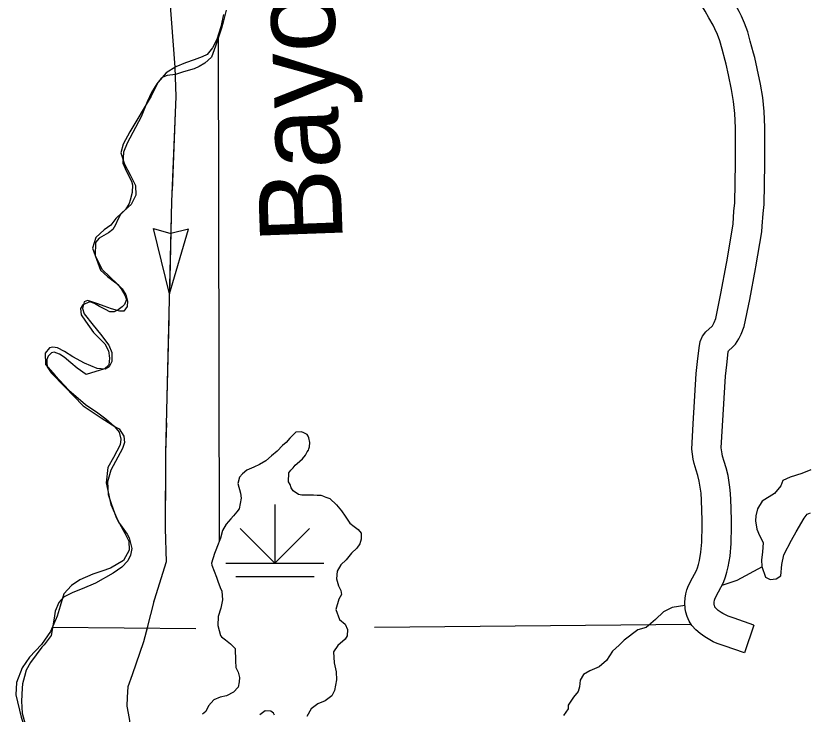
# Model space of a CAD drawing. Extents: x 1373094 to 1376427, y 1168361 to 1170494.
# Drawn here: x 1373397.7 to 1373465.3, y 1169725.9 to 1169785.3 of the extents above; entities that cross this region are included whole.
import ezdxf

# ---------------------------------------------------------------- set-up
doc = ezdxf.new("R2010")
doc.units = 0
doc.layers.add('R_Axis', color=7, linetype='Continuous')

msp = doc.modelspace()

# ---------------------------------------------------------------- linework, layer by layer
at = {"layer": 'R_Axis'}
for p, q in [((1373410.773, 1169761.682), (1373409.424, 1169767.241)), ((1373409.424, 1169767.241), (1373410.885, 1169766.812)), ((1373410.773, 1169761.682), (1373412.384, 1169767.171)), ((1373412.384, 1169767.171), (1373410.905, 1169766.812)), ((1373419.753, 1169743.734), (1373419.753, 1169738.734)), ((1373419.753, 1169738.734), (1373416.806, 1169741.681)), ((1373419.753, 1169738.734), (1373422.699, 1169741.681)), ((1373415.586, 1169738.734), (1373423.919, 1169738.734)), ((1373416.419, 1169737.598), (1373423.086, 1169737.598)), ((1373460.553, 1169733.472), (1373459.741, 1169731.108))]:
    msp.add_line(p, q, dxfattribs=at)
for points in [[(1373412.64, 1169808.408), (1373409.961, 1169801.023), (1373409.712, 1169800.051), (1373409.902, 1169798.585), (1373411.232, 1169780.964)], [(1373458.185, 1169781.213), (1373458.109, 1169781.541), (1373457.84, 1169782.502), (1373457.645, 1169783.212), (1373457.441, 1169783.758), (1373457.227, 1169784.225), (1373457.072, 1169784.541), (1373456.727, 1169785.154), (1373456.391, 1169785.721), (1373456.161, 1169786.091), (1373455.877, 1169786.525), (1373455.671, 1169786.772), (1373455.26, 1169787.252), (1373454.937, 1169787.584), (1373454.807, 1169787.707), (1373454.567, 1169787.915), (1373454.416, 1169788.03)], [(1373460.62, 1169781.779), (1373460.531, 1169782.162), (1373460.249, 1169783.17), (1373460.026, 1169783.981), (1373459.752, 1169784.718), (1373459.485, 1169785.297), (1373459.286, 1169785.704), (1373458.892, 1169786.405), (1373458.537, 1169787.003)], [(1373415.382, 1169785.458), (1373415.152, 1169784.403), (1373414.807, 1169783.312), (1373414.454, 1169782.621), (1373413.983, 1169782.045), (1373413.571, 1169781.854), (1373412.877, 1169781.591), (1373412.151, 1169781.327), (1373411.309, 1169780.994), (1373410.488, 1169780.478), (1373409.821, 1169779.682), (1373409.211, 1169778.502), (1373408.631, 1169777.507), (1373408.003, 1169776.461), (1373407.407, 1169775.449), (1373406.844, 1169774.404), (1373406.625, 1169773.665), (1373406.942, 1169772.704), (1373407.441, 1169771.812), (1373407.89, 1169770.903), (1373407.906, 1169770.069), (1373407.522, 1169769.277), (1373406.737, 1169768.579), (1373406.197, 1169768.085), (1373405.793, 1169767.51), (1373405.218, 1169767.115), (1373404.516, 1169766.451), (1373404.217, 1169765.562), (1373404.9, 1169763.689), (1373405.508, 1169763.15), (1373406.217, 1169762.595), (1373406.741, 1169762.105), (1373407.05, 1169761.593), (1373407.21, 1169761.046), (1373407.185, 1169760.578), (1373406.877, 1169760.188), (1373406.561, 1169760.182), (1373405.826, 1169760.386), (1373405.223, 1169760.608), (1373404.671, 1169760.831), (1373404.069, 1169761.02), (1373403.785, 1169761.099), (1373403.504, 1169760.993), (1373403.365, 1169760.423), (1373403.506, 1169759.975), (1373404.289, 1169759.006), (1373404.902, 1169758.233), (1373405.601, 1169757.311), (1373405.879, 1169756.666), (1373405.859, 1169755.915), (1373405.635, 1169755.46), (1373405.29, 1169755.253), (1373404.607, 1169755.324), (1373403.535, 1169755.771), (1373402.544, 1169756.32), (1373401.838, 1169756.757), (1373401.233, 1169757.063), (1373400.85, 1169757.139), (1373400.568, 1169757.067), (1373400.195, 1169756.61), (1373400.229, 1169755.643), (1373401.028, 1169754.723), (1373402.198, 1169753.46), (1373403.634, 1169752.236), (1373404.661, 1169751.537), (1373405.369, 1169751.017), (1373406.079, 1169750.396), (1373406.504, 1169749.887), (1373406.631, 1169749.288), (1373406.59, 1169748.82), (1373406.012, 1169747.725), (1373405.529, 1169746.882), (1373405.387, 1169745.578), (1373405.77, 1169743.749), (1373406.378, 1169742.376), (1373406.963, 1169741.285), (1373407.308, 1169740.608), (1373407.339, 1169739.857), (1373406.874, 1169738.964), (1373405.756, 1169738.31), (1373405.012, 1169738.062), (1373404.252, 1169737.798)], [(1373415.608, 1169785.815), (1373415.38, 1169784.912), (1373415.216, 1169784.277), (1373414.855, 1169783.274), (1373414.692, 1169782.739), (1373414.364, 1169781.802), (1373413.801, 1169781.299), (1373413.303, 1169781.029), (1373412.872, 1169780.826), (1373411.976, 1169780.555), (1373411.279, 1169780.351), (1373410.581, 1169780.247), (1373410.216, 1169780.111), (1373410.05, 1169779.977), (1373409.687, 1169779.541), (1373409.258, 1169778.804), (1373408.863, 1169778.001), (1373408.37, 1169776.73), (1373407.184, 1169774.487), (1373406.855, 1169773.718), (1373406.793, 1169772.783), (1373407.128, 1169772.084), (1373407.531, 1169771.251), (1373407.632, 1169770.951), (1373407.602, 1169770.283), (1373407.439, 1169769.648), (1373407.34, 1169769.347), (1373407.044, 1169768.845), (1373406.613, 1169768.409), (1373406.383, 1169768.007), (1373406.185, 1169767.539), (1373405.954, 1169767.137), (1373405.59, 1169766.868), (1373405.192, 1169766.632), (1373404.794, 1169766.396), (1373404.464, 1169766.027), (1373404.436, 1169764.892), (1373405.039, 1169763.727), (1373406.375, 1169762.466), (1373406.676, 1169762.1), (1373406.978, 1169761.567), (1373407.112, 1169761.201), (1373406.948, 1169760.766), (1373406.75, 1169760.565), (1373406.418, 1169760.296), (1373406.053, 1169760.127), (1373405.688, 1169760.125), (1373405.321, 1169760.324), (1373404.821, 1169760.588), (1373404.388, 1169760.853), (1373403.988, 1169760.984), (1373403.391, 1169760.747), (1373403.193, 1169760.413), (1373403.262, 1169759.879), (1373403.63, 1169759.347), (1373404.3, 1169758.382), (1373405.268, 1169757.419), (1373405.57, 1169756.82), (1373405.673, 1169756.186), (1373405.609, 1169755.618), (1373405.245, 1169755.283), (1373403.685, 1169754.807), (1373402.918, 1169755.337), (1373402.383, 1169755.802), (1373401.816, 1169756.266), (1373401.416, 1169756.531), (1373400.95, 1169756.695), (1373400.717, 1169756.661), (1373400.453, 1169756.359), (1373400.321, 1169756.091), (1373400.322, 1169755.858), (1373400.357, 1169755.457), (1373400.692, 1169754.958), (1373401.861, 1169753.763), (1373403.431, 1169752.135), (1373404.965, 1169751.108), (1373406.199, 1169750.314), (1373406.499, 1169750.182), (1373406.9, 1169749.55), (1373406.936, 1169749.016), (1373406.772, 1169748.514), (1373406.377, 1169747.778), (1373405.784, 1169746.673), (1373405.489, 1169745.67), (1373405.56, 1169744.602), (1373405.83, 1169743.736), (1373406.201, 1169742.703), (1373406.436, 1169742.236), (1373406.737, 1169741.804), (1373407.172, 1169741.206)], [(1373414.915, 1169783.653), (1373415.01, 1169740.556)], [(1373461.474, 1169772.749), (1373461.495, 1169773.968), (1373461.487, 1169775.288), (1373461.487, 1169775.861), (1373461.433, 1169777.2), (1373461.305, 1169778.381), (1373461.116, 1169779.516), (1373460.839, 1169780.838), (1373460.62, 1169781.779)], [(1373411.232, 1169780.964), (1373411.305, 1169778.46), (1373410.959, 1169769.5), (1373410.452, 1169748.131), (1373410.412, 1169741.702), (1373410.497, 1169738.866), (1373409.464, 1169735.596), (1373408.573, 1169732.046), (1373407.592, 1169729.245), (1373407.24, 1169728.216), (1373407.183, 1169727.346), (1373407.156, 1169726.577), (1373407.338, 1169725.514), (1373407.918, 1169721.692), (1373408.564, 1169716.819), (1373408.889, 1169713.173)], [(1373411.232, 1169780.964), (1373411.282, 1169779.273)], [(1373458.975, 1169772.792), (1373458.995, 1169773.982), (1373458.987, 1169775.281), (1373458.987, 1169775.81), (1373458.938, 1169777.015), (1373458.827, 1169778.041), (1373458.658, 1169779.055), (1373458.398, 1169780.299), (1373458.185, 1169781.212)], [(1373411.252, 1169777.074), (1373410.996, 1169770.479)], [(1373458.232, 1169764.255), (1373458.259, 1169764.396), (1373458.743, 1169767.253), (1373458.774, 1169767.627), (1373458.85, 1169768.706), (1373458.917, 1169769.424), (1373458.975, 1169772.792)], [(1373460.689, 1169763.791), (1373460.72, 1169763.956), (1373461.225, 1169766.939), (1373461.267, 1169767.435), (1373461.342, 1169768.503), (1373461.415, 1169769.287), (1373461.474, 1169772.749)], [(1373410.93, 1169768.28), (1373410.773, 1169761.682)], [(1373455.761, 1169755.91), (1373455.891, 1169757.081), (1373455.979, 1169757.609), (1373456.186, 1169758.07), (1373456.462, 1169758.448), (1373456.99, 1169758.914), (1373457.016, 1169758.942), (1373457.091, 1169759.06), (1373457.17, 1169759.221), (1373457.302, 1169759.583), (1373457.747, 1169761.684), (1373458.232, 1169764.255)], [(1373458.246, 1169755.634), (1373458.368, 1169756.736), (1373458.38, 1169756.806), (1373458.733, 1169757.118), (1373458.996, 1169757.399), (1373459.274, 1169757.832), (1373459.474, 1169758.242), (1373459.711, 1169758.892), (1373460.198, 1169761.193), (1373460.689, 1169763.791)], [(1373410.721, 1169759.483), (1373410.643, 1169756.184)], [(1373410.643, 1169756.184), (1373410.565, 1169752.885)], [(1373455.645, 1169746.657), (1373455.466, 1169747.233), (1373455.389, 1169747.606), (1373455.26, 1169748.452), (1373455.391, 1169750.591), (1373455.648, 1169754.887), (1373455.761, 1169755.91)], [(1373458.033, 1169747.398), (1373457.89, 1169747.858), (1373457.851, 1169748.048), (1373457.772, 1169748.565), (1373457.887, 1169750.44), (1373458.139, 1169754.675), (1373458.246, 1169755.634)], [(1373410.513, 1169750.685), (1373410.452, 1169748.131), (1373410.427, 1169744.086)], [(1373424.021, 1169744.385), (1373423.685, 1169744.492), (1373423.352, 1169744.498), (1373423.052, 1169744.539), (1373422.719, 1169744.546), (1373422.037, 1169744.525), (1373421.752, 1169744.6), (1373421.311, 1169744.904), (1373421.137, 1169745.149), (1373421.062, 1169745.447), (1373420.905, 1169745.676), (1373420.949, 1169746.429), (1373421.109, 1169746.651), (1373421.319, 1169746.858), (1373421.478, 1169747.096), (1373421.657, 1169747.235), (1373422.094, 1169747.632), (1373422.367, 1169747.941), (1373422.509, 1169748.229), (1373422.604, 1169748.366), (1373422.651, 1169748.467), (1373422.696, 1169748.636), (1373422.735, 1169749.004), (1373422.64, 1169749.402), (1373422.585, 1169749.567), (1373422.498, 1169749.698), (1373422.227, 1169749.84), (1373422.009, 1169749.917), (1373421.527, 1169749.903), (1373421.317, 1169749.679), (1373421.027, 1169749.37), (1373420.705, 1169749.009), (1373420.413, 1169748.767), (1373419.946, 1169748.269), (1373419.475, 1169747.87), (1373418.989, 1169747.455), (1373418.449, 1169747.138), (1373417.957, 1169746.923), (1373417.366, 1169746.671), (1373416.992, 1169746.359), (1373416.735, 1169746.068), (1373416.585, 1169745.529), (1373416.826, 1169744.701), (1373416.872, 1169744.285), (1373416.716, 1169743.379), (1373416.524, 1169743.123), (1373416.235, 1169742.763), (1373415.993, 1169742.522), (1373415.607, 1169742.076), (1373415.291, 1169741.516), (1373415.128, 1169740.86), (1373414.819, 1169740.066), (1373414.772, 1169739.981), (1373414.602, 1169739.558), (1373414.344, 1169738.732), (1373414.381, 1169738.583), (1373414.778, 1169737.543), (1373414.888, 1169737.213), (1373415.104, 1169736.685), (1373415.247, 1169736.356), (1373415.285, 1169735.622), (1373415.157, 1169734.9), (1373414.929, 1169734.192), (1373414.885, 1169733.44), (1373415.11, 1169732.595), (1373415.196, 1169732.481), (1373415.553, 1169732.224), (1373415.98, 1169731.87), (1373416.374, 1169731.481), (1373416.406, 1169730.43), (1373416.423, 1169729.863), (1373416.618, 1169729.468), (1373416.747, 1169729.021), (1373416.725, 1169728.654), (1373416.622, 1169728.2), (1373416.236, 1169727.771), (1373415.63, 1169727.452), (1373415.085, 1169727.335), (1373414.543, 1169727.101), (1373414.092, 1169726.604), (1373413.874, 1169726.113), (1373413.598, 1169725.887)], [(1373458.247, 1169737.985), (1373458.366, 1169738.425), (1373458.524, 1169739.352), (1373458.623, 1169740.412), (1373458.623, 1169740.971), (1373458.644, 1169741.368), (1373458.648, 1169741.836), (1373458.648, 1169742.428), (1373458.592, 1169744.231), (1373458.542, 1169744.978), (1373458.474, 1169745.425), (1373458.348, 1169746.197), (1373458.2, 1169746.858), (1373458.033, 1169747.398)], [(1373455.833, 1169738.638), (1373455.921, 1169738.963), (1373456.044, 1169739.679), (1373456.123, 1169740.529), (1373456.124, 1169741.039), (1373456.145, 1169741.444), (1373456.148, 1169741.845), (1373456.148, 1169742.388), (1373456.095, 1169744.109), (1373456.055, 1169744.704), (1373456.005, 1169745.033), (1373455.892, 1169745.723), (1373455.782, 1169746.214), (1373455.645, 1169746.657)], [(1373465.395, 1169746.681), (1373464.623, 1169746.374), (1373463.65, 1169746.077), (1373463.011, 1169745.774), (1373462.841, 1169745.335), (1373462.312, 1169744.668), (1373461.266, 1169744.035), (1373460.871, 1169743.355), (1373460.722, 1169742.783), (1373460.685, 1169742.348), (1373460.806, 1169741.65), (1373461.039, 1169741.09), (1373461.356, 1169740.498), (1373461.297, 1169739.678), (1373461.2, 1169739.041), (1373461.234, 1169738.458), (1373461.544, 1169737.549), (1373461.932, 1169737.36), (1373462.446, 1169737.409), (1373462.838, 1169737.655), (1373462.925, 1169738.642), (1373463.1, 1169739.466), (1373463.762, 1169740.688), (1373464.156, 1169741.418), (1373464.836, 1169742.574), (1373465.092, 1169742.915), (1373465.371, 1169743.041)], [(1373424.021, 1169744.385), (1373424.441, 1169744.247), (1373425.006, 1169743.714), (1373425.42, 1169743.209), (1373425.734, 1169742.751), (1373426.15, 1169742.162), (1373426.508, 1169741.873), (1373426.849, 1169741.616), (1373427.091, 1169741.289), (1373427.106, 1169740.789), (1373427.002, 1169740.402), (1373426.731, 1169740.009), (1373426.294, 1169739.595), (1373425.812, 1169739.03), (1373425.375, 1169738.616), (1373425.059, 1169738.055), (1373425.012, 1169737.403), (1373425.18, 1169736.807), (1373425.375, 1169736.412), (1373425.418, 1169736.079), (1373425.197, 1169735.689), (1373424.941, 1169734.796), (1373425.249, 1169733.954), (1373425.727, 1169733.551), (1373425.94, 1169733.09), (1373425.922, 1169732.572), (1373425.749, 1169732.266), (1373425.116, 1169731.729), (1373424.75, 1169731.184), (1373424.795, 1169730.25), (1373424.983, 1169729.505), (1373425.004, 1169728.821), (1373424.832, 1169727.897), (1373424.612, 1169727.457), (1373424.026, 1169727.038), (1373423.402, 1169726.769), (1373422.832, 1169726.351), (1373422.486, 1169725.689)], [(1373410.413, 1169741.886), (1373410.412, 1169741.702), (1373410.497, 1169738.866), (1373409.464, 1169735.596), (1373409.428, 1169735.451)], [(1373407.172, 1169741.206), (1373407.34, 1169740.906), (1373407.576, 1169740.006), (1373407.446, 1169739.438), (1373407.216, 1169738.936), (1373406.72, 1169738.399), (1373405.991, 1169737.895), (1373404.465, 1169737.052), (1373403.337, 1169736.545), (1373402.541, 1169736.241), (1373401.745, 1169735.836), (1373401.348, 1169735.4), (1373401.052, 1169734.664), (1373400.955, 1169734.063), (1373400.696, 1169732.592), (1373400.101, 1169731.788), (1373399.903, 1169731.587), (1373398.945, 1169730.28), (1373398.582, 1169729.644), (1373398.418, 1169729.109), (1373398.255, 1169728.474), (1373398.224, 1169728.106), (1373398.162, 1169727.004), (1373398.234, 1169725.97), (1373398.538, 1169724.836)], [(1373459.741, 1169731.108), (1373458.034, 1169731.694), (1373457.434, 1169731.911), (1373457.087, 1169732.06), (1373456.647, 1169732.306), (1373456.387, 1169732.466), (1373455.979, 1169732.751), (1373455.614, 1169733.068), (1373455.27, 1169733.443), (1373455.026, 1169733.821), (1373454.856, 1169734.212), (1373454.75, 1169734.581), (1373454.699, 1169734.854), (1373454.657, 1169735.389), (1373454.698, 1169735.757), (1373454.758, 1169736.146), (1373454.854, 1169736.466), (1373454.986, 1169736.829), (1373455.328, 1169737.488), (1373455.666, 1169738.11), (1373455.75, 1169738.346), (1373455.834, 1169738.641), (1373455.833, 1169738.638)], [(1373461.245, 1169738.426), (1373459.099, 1169737.267), (1373457.815, 1169736.829)], [(1373404.252, 1169737.798), (1373403.147, 1169737.327), (1373402.442, 1169736.83), (1373401.773, 1169736.133), (1373401.46, 1169735.093), (1373401.21, 1169734.237), (1373400.653, 1169732.925), (1373399.876, 1169731.826), (1373398.865, 1169730.74), (1373398.234, 1169729.827), (1373397.742, 1169728.6), (1373397.695, 1169727.531), (1373398.146, 1169725.637), (1373398.869, 1169723.431), (1373399.699, 1169721.712), (1373400.452, 1169719.623), (1373400.344, 1169718.286), (1373399.882, 1169715.458)], [(1373460.553, 1169733.472), (1373458.864, 1169734.052), (1373458.355, 1169734.236), (1373458.196, 1169734.305), (1373457.913, 1169734.463), (1373457.759, 1169734.558), (1373457.518, 1169734.726), (1373457.36, 1169734.863), (1373457.256, 1169734.976), (1373457.237, 1169735.006), (1373457.213, 1169735.061), (1373457.185, 1169735.157), (1373457.181, 1169735.181), (1373457.168, 1169735.346), (1373457.177, 1169735.427), (1373457.203, 1169735.594), (1373457.228, 1169735.679), (1373457.28, 1169735.822), (1373457.536, 1169736.316), (1373457.955, 1169737.087), (1373458.132, 1169737.582), (1373458.243, 1169737.972), (1373458.247, 1169737.986)], [(1373454.676, 1169735.144), (1373453.596, 1169734.963), (1373452.858, 1169734.607), (1373452.179, 1169733.952), (1373451.384, 1169733.277), (1373450.675, 1169733.072), (1373449.504, 1169732.201), (1373449.084, 1169731.771), (1373448.501, 1169731.253), (1373447.993, 1169730.453), (1373447.36, 1169729.916), (1373446.588, 1169729.592), (1373446.049, 1169729.258), (1373445.764, 1169728.782), (1373445.698, 1169728.213), (1373445.593, 1169727.809), (1373445.175, 1169727.329), (1373444.746, 1169726.664), (1373444.722, 1169726.346), (1373444.324, 1169725.767)], [(1373400.812, 1169733.3), (1373413.027, 1169733.18)], [(1373408.892, 1169733.317), (1373408.573, 1169732.046), (1373407.592, 1169729.245), (1373407.24, 1169728.216), (1373407.183, 1169727.346), (1373407.171, 1169726.984)], [(1373428.248, 1169733.289), (1373455.201, 1169733.551)], [(1373419.721, 1169725.806), (1373419.633, 1169725.97), (1373419.412, 1169726.147), (1373418.928, 1169726.183), (1373418.473, 1169725.835)]]:
    msp.add_lwpolyline(points, dxfattribs=at)

# ---------------------------------------------------------------- texts
msp.add_text('Bayou', height=7.04, rotation=92.08987, dxfattribs=at).set_placement((1373425.547, 1169766.115))

doc.saveas('drawing.dxf')
